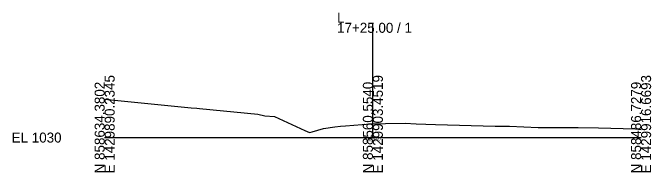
# Model space of a CAD drawing. Extents: x -26 to 153, y -10 to 13058.
# Drawn here: x -25.7 to 152.8, y 11490.3 to 11534.9 of the extents above; entities that cross this region are included whole.
import ezdxf

# ---------------------------------------------------------------- set-up
doc = ezdxf.new("R2010")
doc.units = 0
for name, color, linetype in [('Default', 7, 'Continuous'), ('Exist Cross Section Cell', 7, 'Continuous'), ('Exist XS Center Line Elevation Label', 7, 'Continuous'), ('Exist XS Ground Line', 7, 'Continuous')]:
    doc.layers.add(name, color=color, linetype=linetype)

msp = doc.modelspace()

# ---------------------------------------------------------------- linework, layer by layer
at = {"layer": 'Exist Cross Section Cell'}
for p, q in [((75, 11500), (75, 11532.1)), ((0, 11500), (75, 11500)), ((75, 11500), (150, 11500))]:
    msp.add_line(p, q, dxfattribs=at)
at = {"layer": 'Exist XS Ground Line'}
msp.add_lwpolyline([(0, 11510.7), (24.2, 11508.35), (25.74, 11508.2), (26.5, 11508.14), (42.84, 11506.59), (44.83, 11506.12), (47.47, 11505.85), (55.99, 11502.01), (57.32, 11501.39), (58.01, 11501.59), (61.16, 11502.54), (64.39, 11502.98), (65.94, 11503.21), (67.31, 11503.32), (74.34, 11503.86), (75, 11503.87), (78.52, 11503.95), (84.07, 11504.05), (87.08, 11503.88), (92.55, 11503.64), (109.22, 11503.18), (113.17, 11503.15), (121.26, 11502.83), (122.54, 11502.83), (132.42, 11502.86), (138.09, 11502.69), (148.48, 11502.4), (150, 11502.29)], dxfattribs=at)

# ---------------------------------------------------------------- texts
at = {"layer": 'Default'}
msp.add_text('-', height=0.0001, dxfattribs=at).set_placement((0, 11500))
at = {"layer": 'Exist Cross Section Cell'}
for s, p in [('L', (65, 11532.1)), ('17+25.00 / 1', (65, 11529.3)), ('EL 1030', (-26, 11498.6))]:
    msp.add_text(s, height=2.8, dxfattribs=at).set_placement(p)
for s, p in [('E 1429890.2345', (2.8, 11490)), ('E 1429903.4519', (77.8, 11490)), ('E 1429916.6693', (152.8, 11490)), ('N 858634.3802', (0, 11490)), ('N 858560.5540', (75, 11490)), ('N 858486.7279', (150, 11490))]:
    msp.add_text(s, height=2.8, rotation=90, dxfattribs=at).set_placement(p)
at = {"layer": 'Exist XS Center Line Elevation Label'}
msp.add_text('1033.87', height=0.9, dxfattribs=at).set_placement((72.86, 11498.97))
msp.add_text('1033.87', height=0.9, dxfattribs=at).set_placement((72.86, 11498.97))
msp.add_text('1033.87', height=0.9, dxfattribs=at).set_placement((72.86, 11498.97))

doc.saveas('drawing.dxf')
